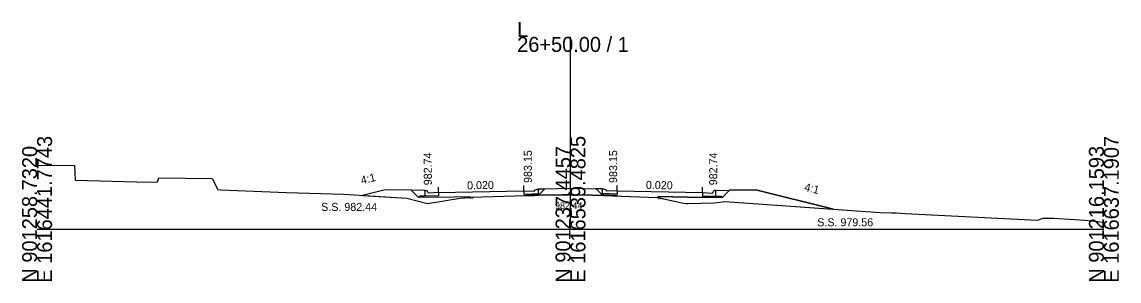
# Model space of a CAD drawing. Extents: x 1009 to 7438, y -1586 to 7964.
# Drawn here: x 2032.1 to 2237.7, y 4414 to 4462.6 of the extents above; entities that cross this region are included whole.
import ezdxf

# ---------------------------------------------------------------- set-up
doc = ezdxf.new("R2010")
doc.units = 0
for name, color, linetype in [('Exist Cross Section Cell', 7, 'Continuous'), ('Exist XS Center Line Elevation Label', 7, 'Continuous'), ('Exist XS Ground Line', 7, 'Continuous'), ('Prop XS Dump Level', 7, 'Continuous'), ('Prop XS Earthwork Shape', 7, 'Continuous'), ('Prop XS EOT Tick Mark', 7, 'Continuous'), ('Prop XS Finish Grade', 7, 'Continuous'), ('Prop XS Finish Grade CurbGutter', 7, 'Continuous'), ('Prop XS Finish Grade Earthwork', 7, 'Continuous'), ('Prop XS Finish Grade Pavement', 7, 'Continuous'), ('Prop XS Hydro Elevations', 7, 'Continuous'), ('Prop XS Pvmt Edge Slope', 7, 'Continuous'), ('Prop XS SE Text', 7, 'Continuous'), ('Prop XS Side Slope Text', 7, 'Continuous'), ('Prop XS SS Elevation Text', 7, 'Continuous'), ('Prop XS Subgrade CurbGutter', 7, 'Continuous'), ('Prop XS Subgrade Earthwork', 7, 'Continuous')]:
    doc.layers.add(name, color=color, linetype=linetype)

msp = doc.modelspace()

# ---------------------------------------------------------------- linework, layer by layer
at = {"layer": 'Exist Cross Section Cell'}
for p, q in [((2134.89, 4423.73), (2134.89, 4459.75)), ((2034.89, 4423.73), (2134.89, 4423.73)), ((2134.89, 4423.73), (2234.89, 4423.73))]:
    msp.add_line(p, q, dxfattribs=at)
at = {"layer": 'Exist XS Ground Line'}
for p, q in [((2034.89, 4435.74), (2041.88, 4435.69)), ((2041.88, 4435.69), (2042.02, 4432.95)), ((2042.02, 4432.95), (2055.91, 4432.58)), ((2055.91, 4432.58), (2057.46, 4432.62)), ((2057.46, 4432.62), (2057.72, 4433.36)), ((2057.72, 4433.36), (2067.7, 4433.25)), ((2067.7, 4433.25), (2068.76, 4431.16)), ((2068.76, 4431.16), (2069.34, 4431.13)), ((2069.34, 4431.13), (2081.63, 4430.61)), ((2081.63, 4430.61), (2092.36, 4430.28)), ((2092.36, 4430.28), (2104.18, 4429.58)), ((2104.18, 4429.58), (2108.06, 4428.57)), ((2108.06, 4428.57), (2114.22, 4429.53)), ((2114.22, 4429.53), (2116.26, 4429.72)), ((2116.26, 4429.72), (2126.51, 4430.03)), ((2126.51, 4430.03), (2128.23, 4430.08)), ((2128.23, 4430.08), (2128.66, 4430.09)), ((2128.66, 4430.09), (2133.33, 4430.19)), ((2133.33, 4430.19), (2134.13, 4430.18)), ((2134.13, 4430.18), (2134.89, 4430.17)), ((2134.89, 4430.17), (2138.95, 4430.11)), ((2138.95, 4430.11), (2141.09, 4430.03)), ((2141.09, 4430.03), (2151.19, 4429.67)), ((2151.19, 4429.67), (2156.06, 4428.65)), ((2156.06, 4428.65), (2156.55, 4428.54)), ((2156.55, 4428.54), (2156.89, 4428.57)), ((2156.89, 4428.57), (2161.86, 4428.66)), ((2161.86, 4428.66), (2163.82, 4428.93)), ((2163.82, 4428.93), (2164.7, 4428.87)), ((2164.7, 4428.87), (2192.95, 4426.88)), ((2192.95, 4426.88), (2195.13, 4426.8)), ((2195.13, 4426.8), (2196.01, 4426.78)), ((2196.01, 4426.78), (2197.62, 4426.67)), ((2197.62, 4426.67), (2222.47, 4425.43)), ((2222.47, 4425.43), (2223.48, 4425.84)), ((2223.48, 4425.84), (2224.09, 4425.81)), ((2224.09, 4425.81), (2225.48, 4425.82)), ((2225.48, 4425.82), (2231.3, 4425.44)), ((2231.3, 4425.44), (2234.89, 4425.09))]:
    msp.add_line(p, q, dxfattribs=at)
at = {"layer": 'Prop XS Dump Level'}
for p, q in [((2110.14, 4430.59), (2126.14, 4430.91)), ((2110.14, 4430.59), (2126.14, 4430.91)), ((2143.64, 4430.91), (2159.64, 4430.59)), ((2143.64, 4430.91), (2159.64, 4430.59))]:
    msp.add_line(p, q, dxfattribs=at)
at = {"layer": 'Prop XS Earthwork Shape'}
for points in [[(2110.14, 4429.76), (2106.39, 4429.69), (2105.05, 4431.03), (2100.14, 4431.13), (2095.9, 4430.07), (2104.18, 4429.58), (2108.06, 4428.57), (2114.22, 4429.53), (2116.04, 4429.7), (2116.04, 4429.79), (2110.14, 4429.68)], [(2130.12, 4431.32), (2134.89, 4431.42), (2139.67, 4431.32), (2139.72, 4431.32), (2140.9, 4430.14), (2143.64, 4430.08), (2143.64, 4430), (2143.64, 4429.94), (2141.09, 4430.03), (2138.95, 4430.11), (2134.89, 4430.17), (2134.13, 4430.18), (2133.33, 4430.19), (2128.66, 4430.09), (2128.23, 4430.08), (2126.51, 4430.03), (2126.14, 4430.02), (2126.14, 4430.08), (2128.89, 4430.14), (2130.07, 4431.32)], [(2164.7, 4428.87), (2184.17, 4427.5), (2169.64, 4431.13), (2164.73, 4431.03), (2163.39, 4429.69), (2159.64, 4429.76), (2159.64, 4429.68), (2151.25, 4429.84), (2151.25, 4429.65), (2156.06, 4428.65), (2156.55, 4428.54), (2156.89, 4428.57), (2161.86, 4428.66), (2163.82, 4428.93)]]:
    msp.add_lwpolyline(points, close=True, dxfattribs=at)
at = {"layer": 'Prop XS EOT Tick Mark'}
for p, q in [((2110.14, 4430.59), (2110.14, 4431.59)), ((2126.14, 4430.91), (2126.14, 4431.91)), ((2143.64, 4430.91), (2143.64, 4431.91)), ((2159.64, 4430.59), (2159.64, 4431.59))]:
    msp.add_line(p, q, dxfattribs=at)
at = {"layer": 'Prop XS Finish Grade'}
for p, q in [((2107.64, 4430.97), (2105.05, 4431.03)), ((2128.89, 4431.29), (2130.12, 4431.32)), ((2140.89, 4431.29), (2139.67, 4431.32)), ((2162.14, 4430.97), (2164.73, 4431.03))]:
    msp.add_line(p, q, dxfattribs=at)
at = {"layer": 'Prop XS Finish Grade CurbGutter'}
for p, q in [((2107.64, 4430.97), (2107.89, 4430.97)), ((2107.89, 4430.97), (2108.02, 4430.94)), ((2108.11, 4430.85), (2108.02, 4430.94)), ((2108.18, 4430.6), (2108.11, 4430.85)), ((2108.27, 4430.51), (2108.18, 4430.6)), ((2108.39, 4430.49), (2108.27, 4430.51)), ((2110.14, 4430.59), (2108.39, 4430.49)), ((2126.14, 4430.91), (2128.14, 4430.87)), ((2128.14, 4431.04), (2128.89, 4431.29)), ((2128.14, 4430.87), (2128.14, 4431.04)), ((2141.64, 4431.04), (2140.89, 4431.29)), ((2141.64, 4430.87), (2141.64, 4431.04)), ((2143.64, 4430.91), (2141.64, 4430.87)), ((2159.64, 4430.59), (2161.39, 4430.49)), ((2161.39, 4430.49), (2161.52, 4430.51)), ((2161.52, 4430.51), (2161.61, 4430.6)), ((2161.61, 4430.6), (2161.68, 4430.85)), ((2161.68, 4430.85), (2161.77, 4430.94)), ((2161.89, 4430.97), (2161.77, 4430.94)), ((2162.14, 4430.97), (2161.89, 4430.97))]:
    msp.add_line(p, q, dxfattribs=at)
at = {"layer": 'Prop XS Finish Grade Earthwork'}
for p, q in [((2100.14, 4431.13), (2095.9, 4430.07)), ((2105.05, 4431.03), (2100.14, 4431.13)), ((2130.12, 4431.32), (2134.89, 4431.42)), ((2134.89, 4431.42), (2139.67, 4431.32)), ((2164.73, 4431.03), (2169.64, 4431.13)), ((2169.64, 4431.13), (2184.17, 4427.5))]:
    msp.add_line(p, q, dxfattribs=at)
at = {"layer": 'Prop XS Finish Grade Pavement'}
for p, q in [((2110.14, 4430.59), (2126.14, 4430.91)), ((2143.64, 4430.91), (2159.64, 4430.59))]:
    msp.add_line(p, q, dxfattribs=at)
at = {"layer": 'Prop XS Pvmt Edge Slope'}
for p, q in [((2127.64, 4430.36), (2128.89, 4430.39)), ((2128.64, 4430.38), (2128.89, 4430.14)), ((2142.14, 4430.36), (2140.89, 4430.39)), ((2141.14, 4430.38), (2140.9, 4430.14)), ((2106.64, 4429.94), (2106.39, 4429.69)), ((2107.64, 4429.96), (2106.64, 4429.94)), ((2162.14, 4429.96), (2163.14, 4429.94)), ((2163.14, 4429.94), (2163.39, 4429.69))]:
    msp.add_line(p, q, dxfattribs=at)
at = {"layer": 'Prop XS Subgrade CurbGutter'}
for p, q in [((2107.64, 4429.96), (2107.64, 4430.97)), ((2110.14, 4430.59), (2110.14, 4430.01)), ((2126.14, 4430.91), (2126.14, 4430.33)), ((2128.89, 4430.39), (2128.89, 4431.29)), ((2140.89, 4430.39), (2140.89, 4431.29)), ((2143.64, 4430.91), (2143.64, 4430.33)), ((2159.64, 4430.59), (2159.64, 4430.01)), ((2162.14, 4429.96), (2162.14, 4430.97)), ((2110.14, 4430.01), (2107.64, 4429.96)), ((2126.14, 4430.33), (2127.64, 4430.36)), ((2143.64, 4430.33), (2142.14, 4430.36)), ((2159.64, 4430.01), (2162.14, 4429.96))]:
    msp.add_line(p, q, dxfattribs=at)
at = {"layer": 'Prop XS Subgrade Earthwork'}
for p, q in [((2106.39, 4429.69), (2105.05, 4431.03)), ((2128.89, 4430.14), (2130.07, 4431.32)), ((2140.9, 4430.14), (2139.72, 4431.32)), ((2163.39, 4429.69), (2164.73, 4431.03)), ((2110.14, 4429.76), (2106.39, 4429.69)), ((2116.04, 4429.79), (2110.14, 4429.68)), ((2110.14, 4429.68), (2110.14, 4429.76)), ((2116.04, 4429.79), (2116.04, 4429.7)), ((2126.14, 4430.08), (2128.89, 4430.14)), ((2126.14, 4430), (2126.14, 4430.08)), ((2126.14, 4430), (2126.14, 4430.02)), ((2143.64, 4430.08), (2140.9, 4430.14)), ((2143.64, 4430), (2143.64, 4430.08)), ((2143.64, 4430), (2143.64, 4429.94)), ((2151.25, 4429.84), (2151.25, 4429.65)), ((2151.25, 4429.84), (2159.64, 4429.68)), ((2159.64, 4429.68), (2159.64, 4429.76)), ((2159.64, 4429.76), (2163.39, 4429.69))]:
    msp.add_line(p, q, dxfattribs=at)

# ---------------------------------------------------------------- texts
at = {"layer": 'Exist Cross Section Cell'}
for s, p in [('L', (2124.89, 4459.75)), ('26+50.00 / 1', (2124.89, 4456.95))]:
    msp.add_text(s, height=2.8, dxfattribs=at).set_placement(p)
for s, p in [('E 1616441.7743', (2037.69, 4413.73)), ('E 1616539.4825', (2137.69, 4413.73)), ('E 1616637.1907', (2237.69, 4413.73)), ('N 901258.7320', (2034.89, 4413.73)), ('N 901237.4457', (2134.89, 4413.73)), ('N 901216.1593', (2234.89, 4413.73))]:
    msp.add_text(s, height=2.8, rotation=90, dxfattribs=at).set_placement(p)
at = {"layer": 'Exist XS Center Line Elevation Label'}
msp.add_text('982.44', height=1.25, dxfattribs=at).set_placement((2131.99, 4427.54))
at = {"layer": 'Prop XS Dump Level'}
for p in [(2116.04, 4429.4), (2116.04, 4429.4), (2151.25, 4429.35), (2151.25, 4429.35)]:
    msp.add_text('Eop', height=0.3, dxfattribs=at).set_placement(p)
at = {"layer": 'Prop XS Hydro Elevations'}
for s, p in [('982.74', (2108.89, 4431.97)), ('983.15', (2127.64, 4432.4)), ('983.15', (2143.64, 4432.4)), ('982.74', (2162.39, 4431.97))]:
    msp.add_text(s, height=1.5, rotation=90, dxfattribs=at).set_placement(p)
at = {"layer": 'Prop XS SE Text'}
for rotation, p in [(1.1458, (2115.52, 4431.2)), (358.8542, (2149.02, 4431.3))]:
    msp.add_text('0.020', height=1.5, rotation=rotation, dxfattribs=at).set_placement(p)
at = {"layer": 'Prop XS Side Slope Text'}
for rotation, p in [(14.0362, (2095.78, 4432.13)), (345.9638, (2178.62, 4430.97))]:
    msp.add_text('4:1', height=1.5, rotation=rotation, dxfattribs=at).set_placement(p)
at = {"layer": 'Prop XS SS Elevation Text'}
for s, p in [('S.S. 982.44', (2088.15, 4427.17)), ('S.S. 979.56', (2181.15, 4424.29))]:
    msp.add_text(s, height=1.5, dxfattribs=at).set_placement(p)

doc.saveas('drawing.dxf')
